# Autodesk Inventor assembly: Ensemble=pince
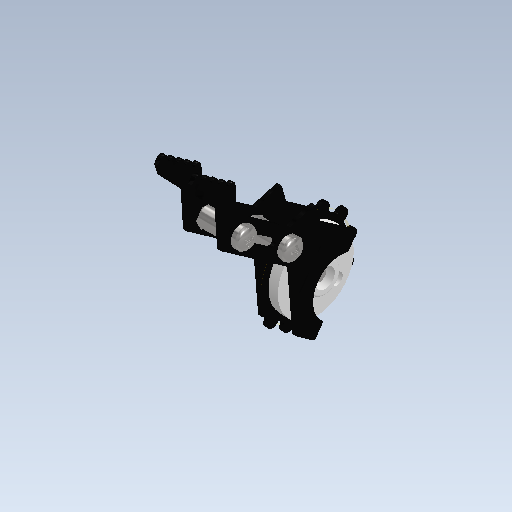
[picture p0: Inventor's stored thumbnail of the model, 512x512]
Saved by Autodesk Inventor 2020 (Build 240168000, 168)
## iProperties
Created: 2021-10
Part Number: Ensemble=pince
Document SubType Name: Assembly
Designer: bruno
Author: bruno
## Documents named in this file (5)
- C:\Users\bruno\Documents\1-Cours-2021-22\1SI\Challenge-2021\Pince-Inventor\Ensemble=pince.iam
- C:\Users\bruno\Documents\1-Cours-2021-22\1SI\Challenge-2021\Pince-Inventor\Ensemble-doigt.iam
- C:\Users\bruno\Documents\1-Cours-2021-22\1SI\Challenge-2021\Pince-Inventor\pince-2.ipt
- C:\Users\bruno\Documents\1-Cours-2021-22\1SI\Challenge-2021\Pince-Inventor\embout-servo.ipt
- C:\Users\bruno\Documents\Inventor\Content Center Files\R2020\fr-FR\ANSI B18.6.7M(01)\ANSI B18.6.7M - M3x0,5 x 5(5).ipt
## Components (6 placed, 4 different names)
1. Ensemble-doigt:1 [sub-assembly] — Logement:1, Placage:1, Placage:2, Angle:1, Placage:8
2. pince-2:1 — Logement:1, Placage:3, Placage:4, Placage:5, Placage:6, Angle:1
3. embout-servo:1 — Placage:1, Placage:2, Placage:7
4. Vis à tête tronconique à empreinte cruciforme - Type IA - Métrique M3x0,5 x 5:1 — Placage:3, Placage:4
5. Vis à tête tronconique à empreinte cruciforme - Type IA - Métrique M3x0,5 x 5:2 — Placage:5, Placage:6
6. Vis à tête tronconique à empreinte cruciforme - Type IA - Métrique M3x0,5 x 5:3 — Placage:7, Placage:8
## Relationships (10: Mate 8, Insert 1, Angle 1)
- Logement:1 [Insert]: Ensemble-doigt:1 ↔ pince-2:1
- Placage:1 [Mate]: Ensemble-doigt:1 ↔ embout-servo:1
- Placage:2 [Mate]: Ensemble-doigt:1 ↔ embout-servo:1
- Placage:3 [Mate]: pince-2:1 ↔ Vis à tête tronconique à empreinte cruciforme - Type IA - Métrique M3x0,5 x 5:1
- Placage:4 [Mate]: pince-2:1 ↔ Vis à tête tronconique à empreinte cruciforme - Type IA - Métrique M3x0,5 x 5:1
- Placage:5 [Mate]: pince-2:1 ↔ Vis à tête tronconique à empreinte cruciforme - Type IA - Métrique M3x0,5 x 5:2
- Placage:6 [Mate]: pince-2:1 ↔ Vis à tête tronconique à empreinte cruciforme - Type IA - Métrique M3x0,5 x 5:2
- Angle:1: Ensemble-doigt:1 ↔ pince-2:1
- Placage:7 [Mate]: embout-servo:1 ↔ Vis à tête tronconique à empreinte cruciforme - Type IA - Métrique M3x0,5 x 5:3
- Placage:8 [Mate]: Ensemble-doigt:1 ↔ Vis à tête tronconique à empreinte cruciforme - Type IA - Métrique M3x0,5 x 5:3
